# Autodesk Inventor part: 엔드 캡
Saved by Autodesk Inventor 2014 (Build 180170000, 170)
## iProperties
Created: 2026-05
Part Number: 엔드 캡
Material: 일반
Document SubType Name: Modeling
Designer: dg
Density: 1 g/cm^3
Appearance: 기본값
Author: dg
Author: jhkim
Creation Date: 2026-04-27
Sending System: Autodesk Inventor 2027
Preprocessor: ST-DEVELOPER v20.1
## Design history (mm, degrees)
node "엔드 캡1"
node "솔리드1"
node "기준1"
